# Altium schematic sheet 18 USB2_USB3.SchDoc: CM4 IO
size 297 x 209 mm; Page Create Date: March  8, 1995; Page Number: 18; Page Size: A4; Comment: radxa_1010; Page Count: 19; RevCode: V1.10; Doc: 18 USB2/USB3; DsnPath: D:\WMS\黄工\[RC126]CM4_IO_V1.10\[RC126]_V1.10\CM4 IO_V1.10.DSN; SchematicName: CM4 IO V1.10; PageName: 18 USB2/USB3; PageSize: A4; TopSchematic: True
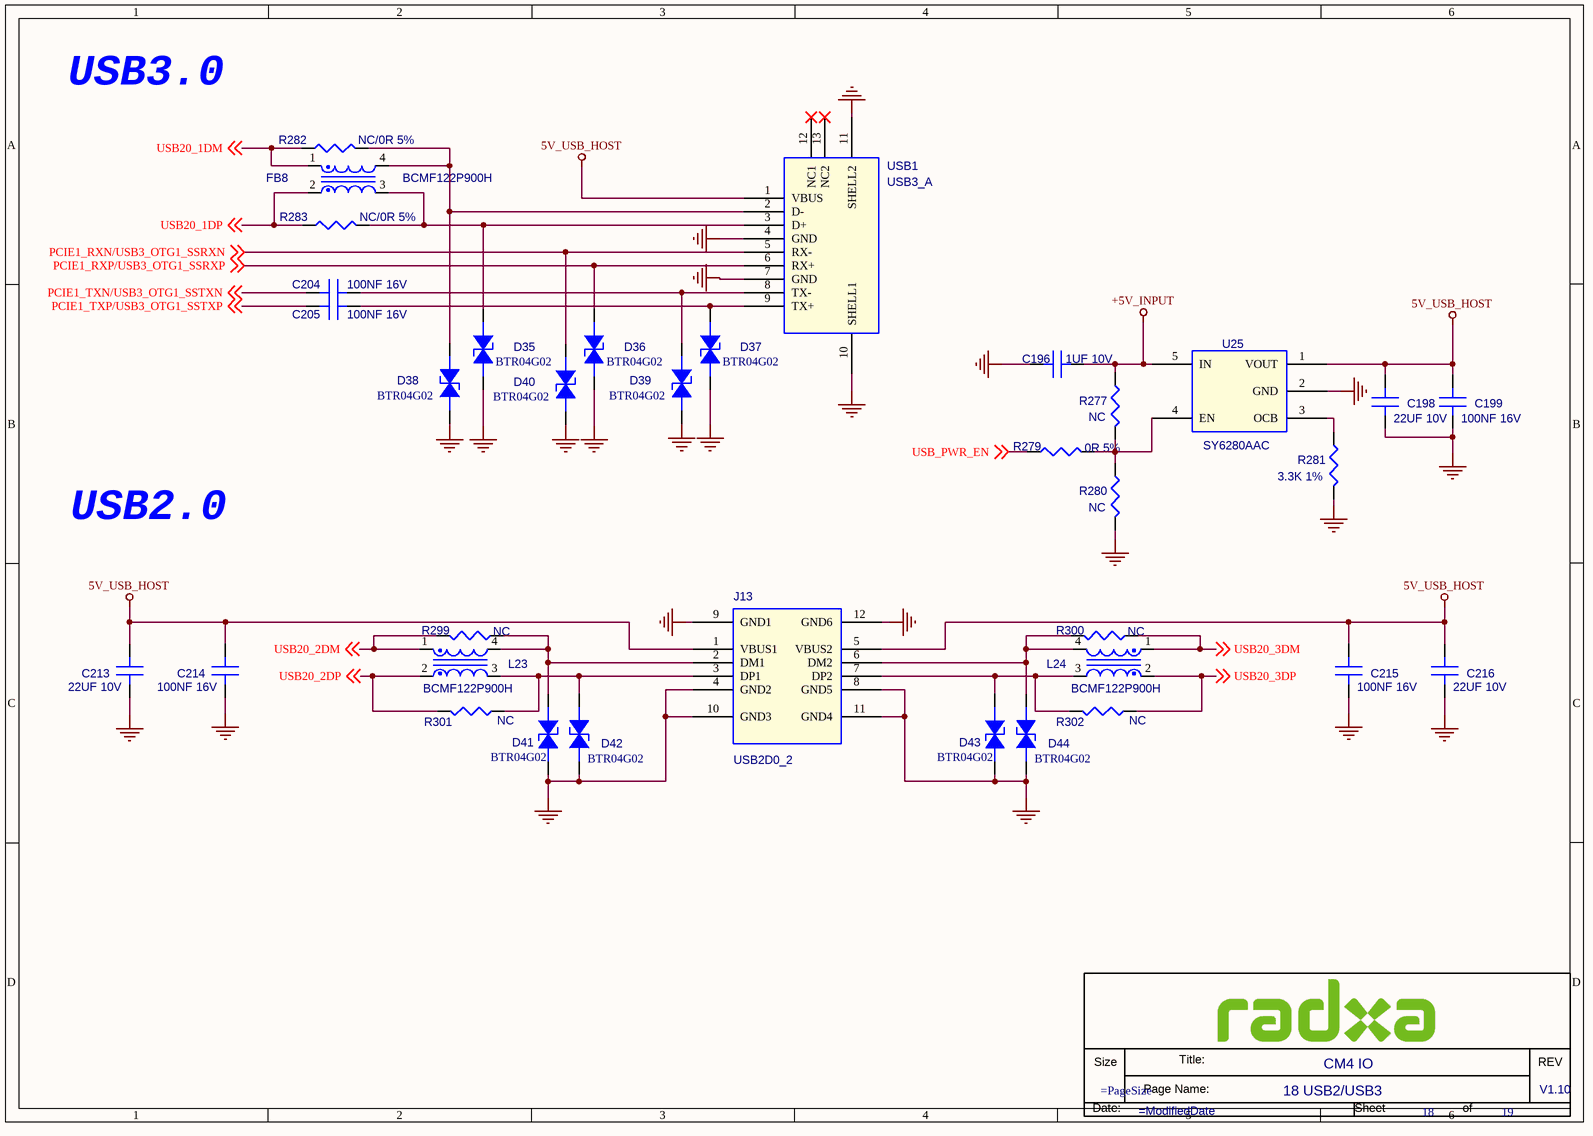
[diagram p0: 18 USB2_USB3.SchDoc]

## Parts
*  Doc: 18 USB2/USB3  RevCode: V1.10  Title: CM4 IO  Page Number: 18  Page Count: 19  (hidden comment: radxa_1010)  (graphical)
C196  1UF 10V  [C0201]
C198  22UF 10V  [C0603]
C199  100NF 16V  [C0201]
C204  100NF 16V  [C0201]
C205  100NF 16V  [C0201]
C213  22UF 10V  [C0603]
C214  100NF 16V  [C0201]
C215  100NF 16V  [C0201]
C216  22UF 10V  [C0603]
D35  BTR04G02  [DFN1006-2L]
D36  BTR04G02  [DFN1006-2L]
D37  BTR04G02  [DFN1006-2L]
D38  BTR04G02  [DFN1006-2L]
D39  BTR04G02  [DFN1006-2L]
D40  BTR04G02  [DFN1006-2L]
D41  BTR04G02  [DFN1006-2L]
D42  BTR04G02  [DFN1006-2L]
D43  BTR04G02  [DFN1006-2L]
D44  BTR04G02  [DFN1006-2L]
FB8  BCMF122P900H  [LC1210]
J13  USB2D0_2  [CON_USB2D0_TH1X2_LIE]
L23  BCMF122P900H  [LC1210]
L24  BCMF122P900H  [LC1210]
R277  NC  [R0402]
R279  0R 5%  [R0402]
R280  NC  [R0402]
R281  3.3K 1%  [R0402]
R282  NC/0R 5%  [R0402]
R283  NC/0R 5%  [R0402]
R299  NC  [R0402]
R300  NC  [R0402]
R301  NC  [R0402]
R302  NC  [R0402]
U25  SY6280AAC  [SOT23_5]
USB1  USB3_A  [USB_SM9_2D0_LIE]

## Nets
5V_USB_HOST: C198.1(A) C199.1(A) C213.1(A) C214.1(A) C215.1(A) C216.1(A) J13.1(VBUS1) J13.5(VBUS2) U25.1(VOUT) USB1.1(VBUS)
+5V_INPUT: C196.1(A) R277.1 U25.5(IN)
GND: C196.2(B) C198.2(B) C199.2(B) C213.2(B) C214.2(B) C215.2(B) C216.2(B) D35.1(ANODE) D36.1(ANODE) D37.1(ANODE) D38.1(ANODE) D39.1(ANODE) D40.1(ANODE) D41.1(ANODE) D42.1(ANODE) D43.1(ANODE) D44.1(ANODE) J13.4(GND2) J13.8(GND5) J13.9(GND1) J13.10(GND3) J13.11(GND4) J13.12(GND6) R280.2 R281.2 U25.2(GND) USB1.4(GND) USB1.7(GND) USB1.10(SHELL1) USB1.11(SHELL2)
PCIE1_RXN/USB3_OTG1_SSRXN: D40.2(CATHODE) USB1.5(RX-) ; off-sheet PCIE1_RXN/USB3_OTG1_SSRXN
PCIE1_RXP/USB3_OTG1_SSRXP: D36.2(CATHODE) USB1.6(RX+) ; off-sheet PCIE1_RXP/USB3_OTG1_SSRXP
PCIE1_TXN/USB3_OTG1_SSTXN: C204.1(A) ; off-sheet PCIE1_TXN/USB3_OTG1_SSTXN
PCIE1_TXP/USB3_OTG1_SSTXP: C205.1(A) ; off-sheet PCIE1_TXP/USB3_OTG1_SSTXP
USB20_1DM: FB8.1 R282.2 ; off-sheet USB20_1DM
USB20_1DP: FB8.2 R283.2 ; off-sheet USB20_1DP
USB20_2DM: L23.1 R299.1 ; off-sheet USB20_2DM
USB20_2DP: L23.2 R301.1 ; off-sheet USB20_2DP
USB20_3DM: L24.1 R300.1 ; off-sheet USB20_3DM
USB20_3DP: L24.2 R302.1 ; off-sheet USB20_3DP
USB_PWR_EN: R279.2 ; off-sheet USB_PWR_EN
NetC204_2: C204.2(B) D39.2(CATHODE) USB1.8(TX-)
NetC205_2: C205.2(B) D37.2(CATHODE) USB1.9(TX+)
NetD35_2: D35.2(CATHODE) FB8.3 R283.1 USB1.3(D+)
NetD38_2: D38.2(CATHODE) FB8.4 R282.1 USB1.2(D-)
NetD41_2: D41.2(CATHODE) J13.2(DM1) L23.4 R299.2
NetD42_2: D42.2(CATHODE) J13.3(DP1) L23.3 R301.2
NetD43_2: D43.2(CATHODE) J13.7(DP2) L24.3 R302.2
NetD44_2: D44.2(CATHODE) J13.6(DM2) L24.4 R300.2
NetR277_2: R277.2 R279.1 R280.1 U25.4(EN)
NetR281_1: R281.1 U25.3(OCB)

Not connected (* = marked no-connect by the designer): USB1 12(NC1)* 13(NC2)*

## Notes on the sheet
- USB3.0
- USB2.0

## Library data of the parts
C196 = C: SMD  0201  1UF  10V  X5R  ±20%  ROHS; PARTS: 1; Part Reference: C196; Part Number: A1C01.00081; OriginalSymbolOrigin: (0,30); PKG_TYPE: CAP2-100-250; LEVEL: STD; PINSWAP: (A,B)
C198 = C: SMD  0603  22UF  10V  X5R  ±20%  ROHS; PARTS: 1; Part Reference: C198; Part Number: A1C01.00015; OriginalSymbolOrigin: (0,30); PKG_TYPE: CAP2-100-250; LEVEL: STD; PINSWAP: (A,B)
C199 = C: SMD  0201  100NF  16V  X5R  ±20%  ROHS; PARTS: 1; Part Reference: C199; Part Number: A1C01.00099; OriginalSymbolOrigin: (0,30); PKG_TYPE: CAP2-100-250; LEVEL: STD; PINSWAP: (A,B); Preferred: 6715f349cd0bc5
C204 = C: SMD  0201  100NF  16V  X5R  ±20%  ROHS; PARTS: 1; Part Reference: C204; Part Number: A1C01.00099; OriginalSymbolOrigin: (0,30); PKG_TYPE: CAP2-100-250; LEVEL: STD; PINSWAP: (A,B); Preferred: 6715f349cd0bc5
C205 = C: SMD  0201  100NF  16V  X5R  ±20%  ROHS; PARTS: 1; Part Reference: C205; Part Number: A1C01.00099; OriginalSymbolOrigin: (0,30); PKG_TYPE: CAP2-100-250; LEVEL: STD; PINSWAP: (A,B); Preferred: 6715f349cd0bc5
C213 = C: SMD  0603  22UF  10V  X5R  ±20%  ROHS; PARTS: 1; Part Reference: C213; Part Number: A1C01.00015; OriginalSymbolOrigin: (0,30); PKG_TYPE: CAP2-100-250; LEVEL: STD; PINSWAP: (A,B)
C214 = C: SMD  0201  100NF  16V  X5R  ±20%  ROHS; PARTS: 1; Part Reference: C214; Part Number: A1C01.00099; OriginalSymbolOrigin: (0,30); PKG_TYPE: CAP2-100-250; LEVEL: STD; PINSWAP: (A,B); Preferred: 6715f349cd0bc5
C215 = C: SMD  0201  100NF  16V  X5R  ±20%  ROHS; PARTS: 1; Part Reference: C215; Part Number: A1C01.00099; OriginalSymbolOrigin: (0,30); PKG_TYPE: CAP2-100-250; LEVEL: STD; PINSWAP: (A,B); Preferred: 6715f349cd0bc5
C216 = C: SMD  0603  22UF  10V  X5R  ±20%  ROHS; PARTS: 1; Part Reference: C216; Part Number: A1C01.00015; OriginalSymbolOrigin: (0,30); PKG_TYPE: CAP2-100-250; LEVEL: STD; PINSWAP: (A,B)
D35 = ESD: SMD  编带  0402  BTR04G02  B-tron  ROHS; Part Reference: D35; Part Number: A1D02.00002; Parameter: ESD-台舟 ESD5341N-封装 esd0402; ID: DE-E0004; Temp Coeff: -50℃ ~ +125℃; PCB Footprint: ESD_D0402
D36 = ESD: SMD  编带  0402  BTR04G02  B-tron  ROHS; Part Reference: D36; Part Number: A1D02.00002; Parameter: ESD-台舟 ESD5341N-封装 esd0402; ID: DE-E0004; Temp Coeff: -50℃ ~ +125℃; PCB Footprint: ESD_D0402
D37 = ESD: SMD  编带  0402  BTR04G02  B-tron  ROHS; Part Reference: D37; Part Number: A1D02.00002; Parameter: ESD-台舟 ESD5341N-封装 esd0402; ID: DE-E0004; Temp Coeff: -50℃ ~ +125℃; PCB Footprint: ESD_D0402
D38 = ESD: SMD  编带  0402  BTR04G02  B-tron  ROHS; Part Reference: D38; Part Number: A1D02.00002; Parameter: ESD-台舟 ESD5341N-封装 esd0402; ID: DE-E0004; Temp Coeff: -50℃ ~ +125℃; PCB Footprint: ESD_D0402
D39 = ESD: SMD  编带  0402  BTR04G02  B-tron  ROHS; Part Reference: D39; Part Number: A1D02.00002; Parameter: ESD-台舟 ESD5341N-封装 esd0402; ID: DE-E0004; Temp Coeff: -50℃ ~ +125℃; PCB Footprint: ESD_D0402
D40 = ESD: SMD  编带  0402  BTR04G02  B-tron  ROHS; Part Reference: D40; Part Number: A1D02.00002; Parameter: ESD-台舟 ESD5341N-封装 esd0402; ID: DE-E0004; Temp Coeff: -50℃ ~ +125℃; PCB Footprint: ESD_D0402
D41 = ESD: SMD  编带  0402  BTR04G02  B-tron  ROHS; Part Reference: D41; Part Number: A1D02.00002; Parameter: ESD-台舟 ESD5341N-封装 esd0402; ID: DE-E0004; Temp Coeff: -50℃ ~ +125℃; PCB Footprint: ESD_D0402
D42 = ESD: SMD  编带  0402  BTR04G02  B-tron  ROHS; Part Reference: D42; Part Number: A1D02.00002; Parameter: ESD-台舟 ESD5341N-封装 esd0402; ID: DE-E0004; Temp Coeff: -50℃ ~ +125℃; PCB Footprint: ESD_D0402
D43 = ESD: SMD  编带  0402  BTR04G02  B-tron  ROHS; Part Reference: D43; Part Number: A1D02.00002; Parameter: ESD-台舟 ESD5341N-封装 esd0402; ID: DE-E0004; Temp Coeff: -50℃ ~ +125℃; PCB Footprint: ESD_D0402
D44 = ESD: SMD  编带  0402  BTR04G02  B-tron  ROHS; Part Reference: D44; Part Number: A1D02.00002; Parameter: ESD-台舟 ESD5341N-封装 esd0402; ID: DE-E0004; Temp Coeff: -50℃ ~ +125℃; PCB Footprint: ESD_D0402
FB8 = MCZ1210AH900L2: SMD  BCMF122P900H  90R  4PIN  不带ESD  ±5%  B-tron  ROHS; Part Reference: FB8; Part Number: A1L03.00003; PCB Footprint: CML_SM4_0D6_1D5
J13 = USB2D0_2: DIP  USB2.0母座  双层  卷边无定位柱  黑色胶芯  17.5*14.4*H15.6mm  90度弯脚  弯脚固定间距15.6mm  铜壳  BUSF082B1N12438  兴联  耐高温  ROHS; Part Reference: J13; Part Number: A1J08.00050; Preferred: 6715f349cd0bc5; Temp Coeff: -25℃ to +105℃
L23 = MCZ1210AH900L2: SMD  BCMF122P900H  90R  4PIN  不带ESD  ±5%  B-tron  ROHS; Part Reference: L23; Part Number: A1L03.00003; PCB Footprint: CML_SM4_0D6_1D5
L24 = MCZ1210AH900L2: SMD  BCMF122P900H  90R  4PIN  不带ESD  ±5%  B-tron  ROHS; Part Reference: L24; Part Number: A1L03.00003; PCB Footprint: CML_SM4_0D6_1D5
R277 = R: SMD  0201  6.8K  1/20W  ±1%  ROHS; Part Reference: R277; Part Number: A1R01.00158; PCB Footprint: R0201
R279 = R: SMD  0201  1K  1/20W  ±5%  ROHS; Part Reference: R279; Part Number: A1R01.00018; PCB Footprint: R0201
R280 = R: SMD  0201  6.8K  1/20W  ±1%  ROHS; Part Reference: R280; Part Number: A1R01.00158; PCB Footprint: R0201
R281 = R: SMD  0201  3.3K  1/20W  ±1%  ROHS; Part Reference: R281; Part Number: A1R01.00178; PCB Footprint: R0201
R282 = R: SMD  0201  0R  1/20W  ±5%  ROHS; Part Reference: R282; Part Number: A1R01.00027; PCB Footprint: R0201; Temp Coeff: －55℃ ~ ＋125℃
R283 = R: SMD  0201  0R  1/20W  ±5%  ROHS; Part Reference: R283; Part Number: A1R01.00027; PCB Footprint: R0201; Temp Coeff: －55℃ ~ ＋125℃
R299 = R: SMD  0201  0R  1/20W  ±5%  ROHS; Part Reference: R299; Part Number: A1R01.00027; PCB Footprint: R0201; Temp Coeff: －55℃ ~ ＋125℃
R300 = R: SMD  0201  0R  1/20W  ±5%  ROHS; Part Reference: R300; Part Number: A1R01.00027; PCB Footprint: R0201; Temp Coeff: －55℃ ~ ＋125℃
R301 = R: SMD  0201  0R  1/20W  ±5%  ROHS; Part Reference: R301; Part Number: A1R01.00027; PCB Footprint: R0201; Temp Coeff: －55℃ ~ ＋125℃
R302 = R: SMD  0201  0R  1/20W  ±5%  ROHS; Part Reference: R302; Part Number: A1R01.00027; PCB Footprint: R0201; Temp Coeff: －55℃ ~ ＋125℃
U25 = SY6280: SMD  USB限流  SY6280AAC  SOT23-5  silergy(矽力杰)  ROHS; Part Reference: U25; Part Number: A1I01.00017
USB1 = USB3_A: SMD  USB3.0母座  单层  直边无定位柱  蓝色胶芯  14.5*13*H6.8mm  90度弯脚  直脚固定间距12.6mm  5001-01010011A  文章济美  鱼叉脚  脚长2.7mm  ROHS; Part Reference: USB1; Part Number: A1J08.00010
